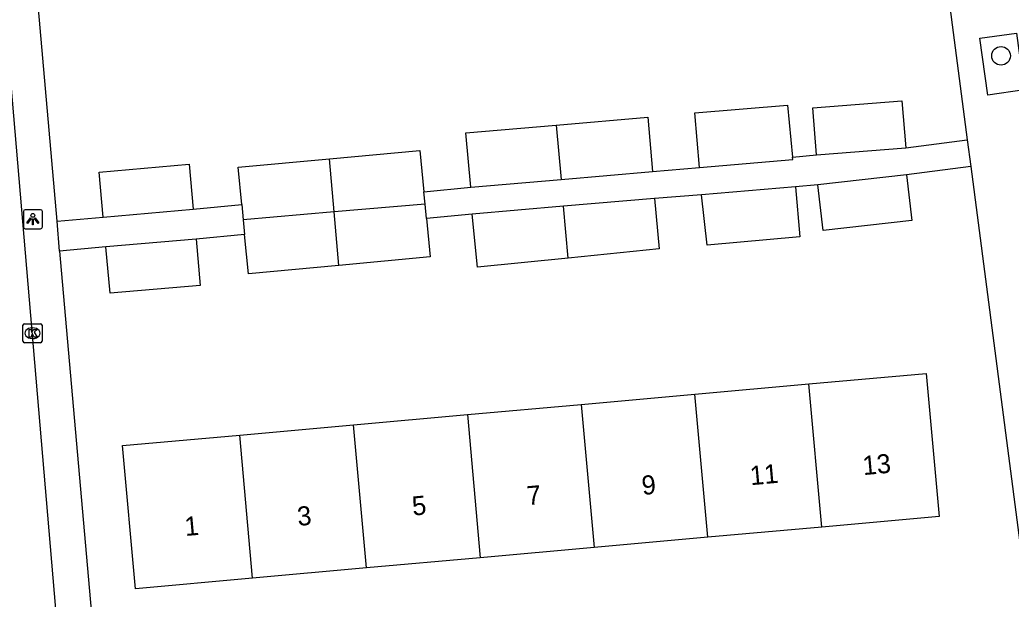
# Model space of a CAD drawing. Extents: x 160557 to 161245, y 385330 to 386505.
# Drawn here: x 161072.6 to 161124.6, y 385573.6 to 385604 of the extents above; entities that cross this region are included whole.
import ezdxf

# ---------------------------------------------------------------- set-up
doc = ezdxf.new("R2010")
doc.units = 0
for name, color, linetype in [('IMGEO_Boom', 7, 'Continuous'), ('IMGEO_Kolk', 7, 'Continuous'), ('IMGEO_Lichtpunt', 7, 'Continuous'), ('IMGEO_Pand', 7, 'Continuous'), ('IMGEO_Pand_nummerreeks', 7, 'Continuous'), ('IMGEO_Rijbaan_lokaal_open', 7, 'Continuous'), ('IMGEO_Voetpad_open', 7, 'Continuous')]:
    doc.layers.add(name, color=color, linetype=linetype)

msp = doc.modelspace()

# ---------------------------------------------------------------- linework, layer by layer
at = {"layer": 'IMGEO_Boom'}
msp.add_circle((161124.106, 385602.126), 0.489, dxfattribs=at)
at = {"layer": 'IMGEO_Kolk'}
for p, q in [((161072.753, 385587.132), (161072.753, 385587.984)), ((161072.828, 385588.058), (161073.68, 385588.058)), ((161073.754, 385587.984), (161073.754, 385587.132)), ((161073.241, 385587.838), (161073.266, 385587.838)), ((161073.68, 385587.058), (161072.828, 385587.058)), ((161073.264, 385587.278), (161073.239, 385587.278))]:
    msp.add_line(p, q, dxfattribs=at)
for points in [[(161072.753, 385587.132), (161072.753, 385587.984)], [(161072.828, 385588.058), (161073.68, 385588.058)], [(161073.754, 385587.984), (161073.754, 385587.132)], [(161073.074, 385587.758), (161073.197, 385587.758), (161073.197, 385587.607), (161073.327, 385587.758), (161073.491, 385587.758), (161073.345, 385587.607), (161073.498, 385587.358), (161073.346, 385587.358), (161073.261, 385587.522), (161073.197, 385587.455), (161073.197, 385587.358), (161073.074, 385587.358), (161073.074, 385587.758)], [(161073.68, 385587.058), (161072.828, 385587.058)]]:
    msp.add_lwpolyline(points, dxfattribs=at)
for centre, start, end in [((161072.83, 385587.982), 91.552, 178.448), ((161072.83, 385587.982), 91.552, 178.448), ((161073.678, 385587.982), 1.552, 88.448), ((161073.678, 385587.982), 1.552, 88.448), ((161072.83, 385587.134), 181.552, 268.448), ((161072.83, 385587.134), 181.552, 268.448), ((161073.678, 385587.134), 271.552, 358.448), ((161073.678, 385587.134), 271.552, 358.448)]:
    msp.add_arc(centre, 0.0765, start, end, dxfattribs=at)
for centre, major_axis, ratio, start_param, end_param in [((161073.24, 385587.558), (-0.387, 0.002), 0.722429, 4.712389, 7.853982), ((161073.265, 385587.558), (-0.39, 0.002), 0.717154, 1.570796, 4.712389)]:
    msp.add_ellipse(centre, major_axis=major_axis, ratio=ratio, start_param=start_param, end_param=end_param, dxfattribs=at)
at = {"layer": 'IMGEO_Lichtpunt'}
for p, q in [((161072.775, 385593.949), (161072.775, 385593.142)), ((161072.775, 385593.949), (161072.775, 385593.142)), ((161073.677, 385594.044), (161072.869, 385594.044)), ((161073.677, 385594.044), (161072.869, 385594.044)), ((161073.771, 385593.142), (161073.771, 385593.949)), ((161073.771, 385593.142), (161073.771, 385593.949)), ((161072.869, 385593.048), (161073.677, 385593.048)), ((161072.869, 385593.048), (161073.677, 385593.048))]:
    msp.add_line(p, q, dxfattribs=at)
for points in [[(161073.149, 385593.613), (161073.188, 385593.585), (161073, 385593.323), (161072.962, 385593.35), (161073.149, 385593.613)], [(161073.251, 385593.565), (161073.298, 385593.565), (161073.298, 385593.243), (161073.251, 385593.243), (161073.251, 385593.565)], [(161073.361, 385593.585), (161073.399, 385593.612), (161073.586, 385593.35), (161073.547, 385593.322), (161073.361, 385593.585)]]:
    msp.add_lwpolyline(points, dxfattribs=at)
msp.add_circle((161073.274, 385593.747), 0.0994, dxfattribs=at)
for centre, start, end in [((161072.869, 385593.949), 90, 180), ((161072.869, 385593.949), 90, 180), ((161073.677, 385593.949), 0, 90), ((161073.677, 385593.949), 0, 90), ((161072.869, 385593.142), 180, 270), ((161072.869, 385593.142), 180, 270), ((161073.677, 385593.142), 270, 0), ((161073.677, 385593.142), 270, 360)]:
    msp.add_arc(centre, 0.0946, start, end, dxfattribs=at)
at = {"layer": 'IMGEO_Pand'}
for points in [[(161108.278, 385596.26), (161108.031, 385599.126), (161112.895, 385599.527), (161113.156, 385596.801)], [(161114.426, 385596.923), (161114.231, 385599.398), (161118.906, 385599.767), (161119.102, 385597.293)], [(161100.756, 385598.486), (161105.554, 385598.901), (161105.804, 385596.047)], [(161096.265, 385595.227), (161096.004, 385598.074), (161100.756, 385598.486)], [(161100.756, 385598.486), (161101.012, 385595.635)], [(161088.847, 385596.719), (161093.589, 385597.162), (161093.802, 385594.986)], [(161108.278, 385596.26), (161113.168, 385596.681), (161113.156, 385596.801)], [(161114.426, 385596.923), (161119.102, 385597.293)], [(161076.962, 385593.658), (161076.756, 385596.014), (161081.488, 385596.428), (161081.693, 385594.072)], [(161084.239, 385594.315), (161084.052, 385596.272), (161088.847, 385596.719)], [(161089.096, 385593.925), (161088.847, 385596.719)], [(161101.012, 385595.635), (161105.804, 385596.047)], [(161119.148, 385595.876), (161119.419, 385593.477), (161114.76, 385592.95), (161114.486, 385595.35)], [(161119.148, 385595.876), (161114.486, 385595.35)], [(161096.265, 385595.227), (161101.012, 385595.635)], [(161113.317, 385595.251), (161113.541, 385592.614), (161108.677, 385592.188), (161108.377, 385594.834)], [(161113.317, 385595.251), (161108.377, 385594.834)], [(161093.865, 385594.341), (161093.802, 385594.986)], [(161084.239, 385594.315), (161084.316, 385593.508)], [(161093.865, 385594.341), (161089.096, 385593.925)], [(161093.94, 385593.582), (161093.865, 385594.341)], [(161101.139, 385594.223), (161096.338, 385593.817)], [(161105.919, 385594.627), (161101.139, 385594.223)], [(161101.383, 385591.505), (161101.139, 385594.223)], [(161105.919, 385594.627), (161106.15, 385591.988), (161101.383, 385591.505)], [(161076.962, 385593.658), (161081.693, 385594.072)], [(161089.096, 385593.925), (161084.316, 385593.508)], [(161089.333, 385591.117), (161089.096, 385593.925)], [(161101.383, 385591.505), (161096.612, 385591.022), (161096.338, 385593.817)], [(161084.316, 385593.508), (161084.389, 385592.743)], [(161093.94, 385593.582), (161094.137, 385591.571), (161089.333, 385591.117)], [(161089.333, 385591.117), (161084.587, 385590.668), (161084.389, 385592.743)], [(161081.846, 385592.5), (161082.057, 385590.069), (161077.326, 385589.654), (161077.113, 385592.086)], [(161081.846, 385592.5), (161077.113, 385592.086)], [(161114.014, 385584.895), (161120.175, 385585.449), (161120.851, 385577.929), (161114.69, 385577.375)], [(161108.038, 385584.358), (161114.014, 385584.895)], [(161114.69, 385577.375), (161114.014, 385584.895)], [(161102.063, 385583.821), (161108.038, 385584.358)], [(161108.714, 385576.838), (161108.038, 385584.358)], [(161096.087, 385583.284), (161102.063, 385583.821)], [(161102.063, 385583.821), (161102.739, 385576.301)], [(161090.111, 385582.746), (161096.087, 385583.284)], [(161096.087, 385583.284), (161096.763, 385575.764)], [(161084.135, 385582.209), (161090.111, 385582.746)], [(161090.787, 385575.226), (161090.111, 385582.746)], [(161084.811, 385574.689), (161078.656, 385574.136), (161077.98, 385581.656), (161084.135, 385582.209)], [(161084.811, 385574.689), (161084.135, 385582.209)], [(161114.69, 385577.375), (161108.714, 385576.838)], [(161108.714, 385576.838), (161102.739, 385576.301)], [(161102.739, 385576.301), (161096.763, 385575.764)], [(161096.763, 385575.764), (161090.787, 385575.226)], [(161090.787, 385575.226), (161084.811, 385574.689)]]:
    msp.add_lwpolyline(points, dxfattribs=at)
at = {"layer": 'IMGEO_Rijbaan_lokaal_open'}
msp.add_lwpolyline([(161070.591, 385618.12), (161070.675, 385617.407), (161070.927, 385614.424), (161074.538, 385572.239)], dxfattribs=at)
at = {"layer": 'IMGEO_Voetpad_open'}
for points in [[(161119.032, 385622.982), (161122.332, 385597.715)], [(161074.543, 385593.446), (161072.34, 385618.545)], [(161123.407, 385600.062), (161122.998, 385603.05), (161124.916, 385603.323), (161125.314, 385600.346), (161123.407, 385600.062)], [(161119.102, 385597.293), (161122.332, 385597.715)], [(161122.332, 385597.715), (161122.515, 385596.316)], [(161113.156, 385596.801), (161114.426, 385596.923)], [(161105.804, 385596.047), (161108.278, 385596.26)], [(161122.515, 385596.316), (161119.148, 385595.876)], [(161122.515, 385596.316), (161125.326, 385574.791)], [(161093.802, 385594.986), (161096.265, 385595.227)], [(161114.486, 385595.35), (161113.317, 385595.251)], [(161108.377, 385594.834), (161105.919, 385594.627)], [(161081.693, 385594.072), (161084.239, 385594.315)], [(161074.543, 385593.446), (161076.962, 385593.658)], [(161096.338, 385593.817), (161093.94, 385593.582)], [(161074.681, 385591.873), (161074.543, 385593.446)], [(161084.389, 385592.743), (161081.846, 385592.5)], [(161077.113, 385592.086), (161074.681, 385591.873)], [(161074.681, 385591.873), (161076.441, 385571.826)]]:
    msp.add_lwpolyline(points, dxfattribs=at)

# ---------------------------------------------------------------- texts
at = {"layer": 'IMGEO_Pand_nummerreeks'}
for s, p in [('13', (161116.879, 385580.102)), ('11', (161110.965, 385579.571)), ('9', (161105.282, 385579.06)), ('7', (161099.254, 385578.518)), ('5', (161093.226, 385577.976)), ('3', (161087.198, 385577.434)), ('1', (161081.283, 385576.902))]:
    msp.add_text(s, height=1, rotation=5.1366, dxfattribs=at).set_placement(p)

doc.saveas('drawing.dxf')
